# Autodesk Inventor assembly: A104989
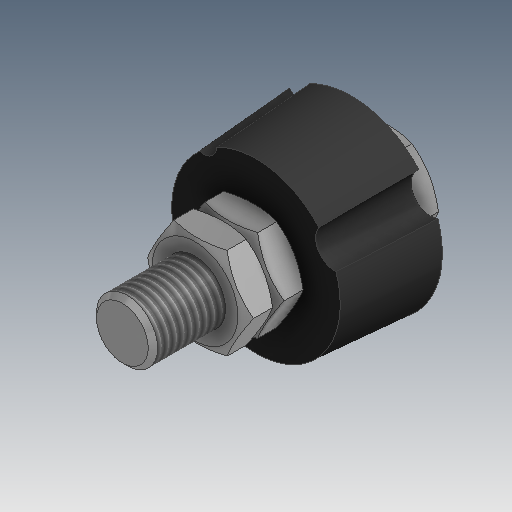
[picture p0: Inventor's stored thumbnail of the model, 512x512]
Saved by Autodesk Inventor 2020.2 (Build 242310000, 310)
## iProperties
Created: 2000-02
Part Number: A104989
Document SubType Name: Assembly
Description: BUSHING,T/L,.625B IDLER
Designer: gpurviance
Mass: 443.504 g
Surface Area: 157.757 cm^2
Volume: 56.5215 cm^3
Density: 7.84664 g/cm^3
Control State: 0
Checked Out: False
Master: False
Shininess: 0.0
Length Units: 11269
Angle Units: 11279
Time Units: 11290
Mass Units: 11283
Length Display Precision: 3
Angle Display Precision: 2
Compacted: True
Dimensions: 47,6x70x47,6 mm
Mass: 0,444 kg
DocNumber: A104989.iam
Folder: 01 - Themengebiete\Simplification\01 - Packaging machine\
VDS_Category: 3D Komponenten
Density: 0.0
Volumn: 0.0
Area: 0.0
PropertySet Name: Model Information
Author: gpurviance
Revision Number: -
Title: clamp
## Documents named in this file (4)
- D:\07 - DEMODATEN\OTX 2019 - Dataset - UPDATE - Dez2019\Designs\07-Packing machine\A104989.iam
- D:\07 - DEMODATEN\OTX 2019 - Dataset - UPDATE - Dez2019\Designs\07-Packing machine\Parts\ADSK-011777.ipt
- D:\07 - DEMODATEN\OTX 2019 - Dataset - UPDATE - Dez2019\Content Center Files\de-DE\DIN EN 24 017\ISO 4017 - M16 x 60DIN EN.ipt
- D:\07 - DEMODATEN\OTX 2019 - Dataset - UPDATE - Dez2019\Content Center Files\de-DE\ISO 4035(2)\ISO 4035 - M16 - ISO.ipt
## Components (4 placed, 3 different names)
1. ADSK-011777:1 — Passend:2
2. DIN EN 24017 M16 x 60:1
3. ISO 4035 M16:1 — Passend:2, Einfügen:4
4. ISO 4035 M16:2 — Einfügen:4
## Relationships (2: Mate 1, Insert 1)
- Passend:2 [Mate]: ADSK-011777:1 ↔ ISO 4035 M16:1
- Einfügen:4 [Insert]: ISO 4035 M16:1 ↔ ISO 4035 M16:2
